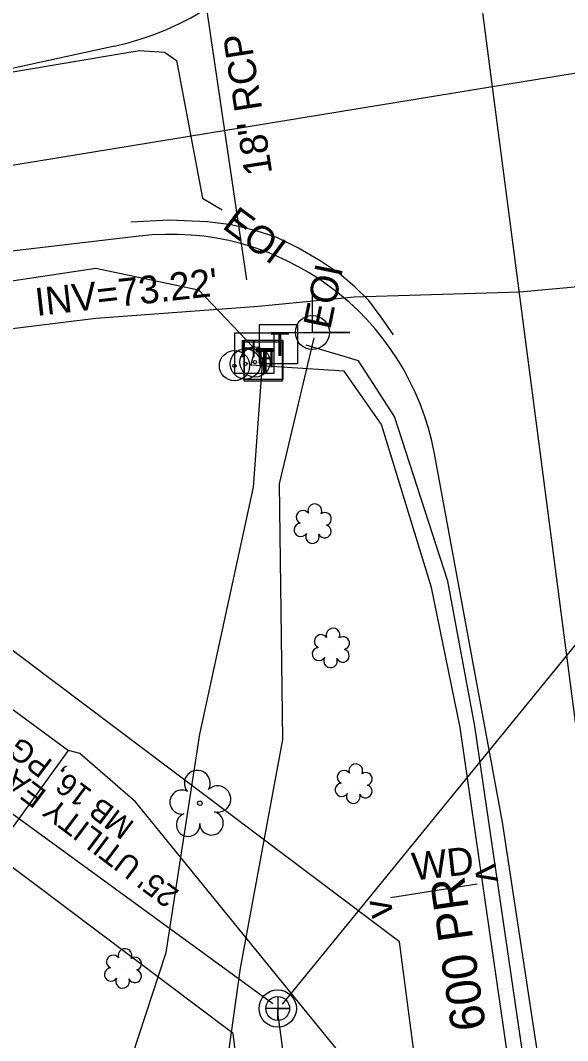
# Model space of a CAD drawing. Extents: x 2364404 to 2371833, y 798876 to 809754.
# Drawn here: x 2368313.6 to 2368392.4, y 807813.1 to 807960.2 of the extents above; entities that cross this region are included whole.
import ezdxf

# ---------------------------------------------------------------- set-up
doc = ezdxf.new("R2010")
doc.units = 0
for name, color, linetype in [('Exist Other Culture Located Object CELL', 7, 'Continuous'), ('Exist Right of Way Easement Line', 7, 'Continuous'), ('Exist Right of Way Easement Line Text', 7, 'Continuous'), ('Exist Right of Way Line', 7, 'Continuous'), ('Exist Roads EOP', 7, 'Continuous'), ('Exist Roads EOT', 7, 'Continuous'), ('Exist Structure Minor Footbridge', 7, 'Continuous'), ('Exist Structure Minor Footbridge Terminator', 7, 'Continuous'), ('Exist Structure Minor Footbridge Text', 7, 'Continuous'), ('Exist Structure Minor Pipes RCP 18 Inch', 7, 'Continuous'), ('Exist Structure Minor Pipes RCP 18 Inch Invert', 7, 'Continuous'), ('Exist Structure Minor Pipes RCP 18 Inch Text', 7, 'Continuous'), ('Exist Utilities Gas UG Line SUE LOS B', 7, 'Continuous'), ('Exist Utilities Other Located Object CELL', 7, 'Continuous'), ('Exist Utilities Other Unknown UG SUE LOS B', 7, 'Continuous'), ('Exist Utilities Other Unknown UG SUE LOS B Text', 7, 'Continuous'), ('Exist Utilities Power Joint Use Telephone CELL', 7, 'Continuous'), ('Exist Utilities Sanitary Sewer Manhole CELL', 7, 'Continuous'), ('Exist Utilities Sanitary Sewer UG Line', 7, 'Continuous'), ('Exist Utilities Telephone Hand Hole CELL', 7, 'Continuous'), ('Exist Utilities Telephone Pedestal CELL', 7, 'Continuous'), ('Exist Utilities Telephone UG Cable SUE LOS C', 7, 'Continuous'), ('Exist Utilities Telephone UG Cable SUE LOS C Text', 7, 'Continuous'), ('Exist Utilities TV UG Cable SUE LOS B', 7, 'Continuous'), ('Exist Utilities Water UG Line SUE LOS B', 7, 'Continuous'), ('Exist Vegetation Shrub CELL', 7, 'Continuous'), ('Exist Vegetation Tree CELL', 7, 'Continuous'), ('Prop Horizontal Alignment', 7, 'Continuous')]:
    doc.layers.add(name, color=color, linetype=linetype)

msp = doc.modelspace()

# ---------------------------------------------------------------- linework, layer by layer
at = {"layer": 'Exist Other Culture Located Object CELL'}
for centre, radius in [((2368347.36, 807910.96), 2.18), ((2368344.41, 807910.43), 2.18), ((2368344.41, 807910.43), 0.24), ((2368347.36, 807910.96), 0.24)]:
    msp.add_circle(centre, radius, dxfattribs=at)
at = {"layer": 'Exist Right of Way Easement Line'}
for p, q in [((2368344.2, 807814.14), (2368262.99, 807875.33)), ((2368511.71, 806538.64), (2368344.2, 807814.14))]:
    msp.add_line(p, q, dxfattribs=at)
at = {"layer": 'Exist Right of Way Line'}
for p, q in [((2368368.2, 807827.36), (2368269.46, 807901.75)), ((2368533.02, 806560.45), (2368368.2, 807827.36))]:
    msp.add_line(p, q, dxfattribs=at)
at = {"layer": 'Exist Roads EOP'}
for points in [[(2368327.15, 807956.52), (2368274.91, 807945.11), (2368232.58, 807936.97), (2368180.11, 807928.25), (2368127.18, 807919.09), (2368078.92, 807911.06), (2368034.07, 807903.44), (2367984.59, 807895.5), (2367945.39, 807888.89), (2367894.54, 807880.53), (2367863.53, 807875.21)], [(2368330.68, 807929.12), (2368282.89, 807923.49), (2368257.36, 807919.77), (2368235.72, 807916.02), (2368181.87, 807907), (2368154.26, 807902.43), (2368131.05, 807898.62), (2368082.95, 807890.29), (2368062.8, 807887.28), (2368038.08, 807883.12), (2367986.91, 807874.75), (2367949.87, 807868.19), (2367928.8, 807864.78), (2367897.29, 807860.14), (2367866.78, 807854.91)], [(2368458.85, 807273.24), (2368452.4, 807323.88), (2368446.15, 807368.12), (2368444.02, 807369.35), (2368441.6, 807369.34), (2368439.16, 807392.12), (2368442.82, 807396.21), (2368435.2, 807454.89), (2368429.11, 807503.15), (2368423.49, 807547.61), (2368418.51, 807586.84), (2368409.79, 807654.27), (2368402.88, 807704.72), (2368396.58, 807752.35), (2368389.7, 807800.7), (2368383.01, 807844.61), (2368373.21, 807897.74)]]:
    msp.add_lwpolyline(points, dxfattribs=at)
for centre, radius, start, end in [((2368318.26, 807997.19), 41.63, 282.3292, 6.5581), ((2368335.2, 807890.73), 38.65, 10.443, 96.7131)]:
    msp.add_arc(centre, radius, start, end, dxfattribs=at)
at = {"layer": 'Exist Roads EOT'}
msp.add_lwpolyline([(2368367.31, 807914.9), (2368365.55, 807917.42), (2368363.75, 807919.85), (2368361.77, 807921.82), (2368359.5, 807923.71), (2368356.75, 807925.55), (2368353.62, 807927.37), (2368350.43, 807928.97), (2368347.53, 807929.88), (2368344, 807930.77), (2368340.52, 807931.16), (2368335.02, 807931.4), (2368329.49, 807931.14)], dxfattribs=at)
at = {"layer": 'Exist Structure Minor Footbridge'}
msp.add_line((2368379.39, 807835.67), (2368366.9, 807833.7), dxfattribs=at)
at = {"layer": 'Exist Structure Minor Pipes RCP 18 Inch'}
msp.add_line((2368339.25, 807969.69), (2368346.16, 807922.83), dxfattribs=at)
at = {"layer": 'Exist Utilities Gas UG Line SUE LOS B'}
msp.add_lwpolyline([(2367870.54, 807838.09), (2367919.9, 807848.3), (2367968.48, 807855.53), (2368019.02, 807864.91), (2368064.26, 807872.88), (2368067.9, 807873.62), (2368094.51, 807877.58), (2368117.72, 807881.71), (2368161.92, 807888.8), (2368216.03, 807898.12), (2368260.65, 807907.32), (2368261.62, 807907.37), (2368282.45, 807912.12), (2368324.46, 807917.31), (2368347.86, 807919.04), (2368361.63, 807920.36), (2368385.5, 807921.08), (2368411.16, 807923.46), (2368412.54, 807923.08), (2368413.42, 807922.79)], dxfattribs=at)
at = {"layer": 'Exist Utilities Other Located Object CELL'}
for radius in [2.18, 0.24]:
    msp.add_circle((2368345.99, 807910.69), radius, dxfattribs=at)
at = {"layer": 'Exist Utilities Other Unknown UG SUE LOS B'}
msp.add_lwpolyline([(2367865.57, 807879.8), (2367916.68, 807886.76), (2367964.49, 807894.84), (2368013.92, 807902.8), (2368064.67, 807911.52), (2368112.58, 807919.65), (2368160.35, 807927.6), (2368209.07, 807936.09), (2368258.24, 807944.17), (2368305.66, 807951.87), (2368307.29, 807951.95), (2368330.7, 807955.87), (2368334.34, 807955.66), (2368336.05, 807954.46), (2368339.82, 807934.59), (2368342.66, 807932.92)], dxfattribs=at)
at = {"layer": 'Exist Utilities Power Joint Use Telephone CELL'}
msp.add_line((2368355.63, 807915.24), (2368355.63, 807915.24), dxfattribs=at)
msp.add_lwpolyline([(2368349.69, 807915.24), (2368361.03, 807915.2), (2368355.63, 807915.22), (2368355.63, 807920.86)], dxfattribs=at)
msp.add_circle((2368355.63, 807915.24), 2.45, dxfattribs=at)
at = {"layer": 'Exist Utilities Sanitary Sewer Manhole CELL'}
msp.add_lwpolyline([(2368350.64, 807819.46), (2368350.64, 807816.04), (2368350.64, 807817.75), (2368352.35, 807817.75), (2368348.93, 807817.75)], dxfattribs=at)
for radius in [2.69, 1.71]:
    msp.add_circle((2368350.64, 807817.75), radius, dxfattribs=at)
at = {"layer": 'Exist Utilities Sanitary Sewer UG Line'}
for p, q in [((2368351.33, 807818.39), (2368447.04, 807935.85)), ((2368349.94, 807818.43), (2368262.9, 807881.9)), ((2368403.25, 807424.76), (2368350.71, 807816.86))]:
    msp.add_line(p, q, dxfattribs=at)
at = {"layer": 'Exist Utilities Telephone Hand Hole CELL'}
for p, q in [((2368344.4, 807915.11), (2368344.4, 807909.38)), ((2368350.12, 807915.11), (2368344.4, 807915.11)), ((2368350.12, 807909.38), (2368350.12, 807915.11)), ((2368347.26, 807912.25), (2368347.26, 807912.25)), ((2368344.4, 807909.38), (2368350.12, 807909.38))]:
    msp.add_line(p, q, dxfattribs=at)
at = {"layer": 'Exist Utilities Telephone Pedestal CELL'}
for p, q in [((2368350.69, 807913.56), (2368350.69, 807913.56)), ((2368348.47, 807911.08), (2368348.47, 807911.08)), ((2368348.56, 807911.3), (2368348.56, 807911.3))]:
    msp.add_line(p, q, dxfattribs=at)
for points in [[(2368347.97, 807910.74), (2368353.56, 807910.74), (2368353.56, 807916.33), (2368347.97, 807916.33), (2368347.97, 807910.74)], [(2368345.75, 807908.25), (2368351.34, 807908.25), (2368351.34, 807913.84), (2368345.75, 807913.84), (2368345.75, 807908.25)], [(2368345.83, 807908.47), (2368351.43, 807908.47), (2368351.43, 807914.07), (2368345.83, 807914.07), (2368345.83, 807908.47)]]:
    msp.add_lwpolyline(points, dxfattribs=at)
at = {"layer": 'Exist Utilities Telephone UG Cable SUE LOS C'}
for points in [[(2368104.4, 807876.72), (2368103.94, 807878.32), (2368103.75, 807883), (2368105.99, 807887.59), (2368109.41, 807889.3), (2368116.46, 807890.7), (2368160.35, 807897.88), (2368214.89, 807907.23), (2368259.58, 807914.4), (2368278.5, 807917.6), (2368324.44, 807924.48), (2368339.22, 807921.35), (2368348.06, 807912.11)], [(2368389.8, 807477.23), (2368411.52, 807479.13), (2368426.75, 807483.79), (2368423.25, 807515.6), (2368416.95, 807563.1), (2368411.16, 807611.97), (2368408.13, 807633.66), (2368404.45, 807661.14), (2368400.96, 807692.3), (2368397.77, 807710.8), (2368392.17, 807754.58), (2368386.02, 807810.85), (2368379.04, 807858.46), (2368375.16, 807879.37), (2368367.44, 807903.09), (2368362.27, 807911.13), (2368354.75, 807913.38)], [(2368318.86, 807794.83), (2368327.7, 807804.86), (2368334.56, 807825.83), (2368339.43, 807857.32), (2368347.17, 807892.9), (2368348.48, 807911.35), (2368348.06, 807912.11)], [(2368377.99, 807750.39), (2368378.54, 807751.1), (2368388.6, 807755.78), (2368389.93, 807760.2), (2368383.78, 807810.78), (2368376.94, 807858.27), (2368372.8, 807878.46), (2368365.61, 807901.95), (2368360.23, 807909.67), (2368346.77, 807910.53), (2368347.26, 807912.25)]]:
    msp.add_lwpolyline(points, dxfattribs=at)
at = {"layer": 'Exist Utilities TV UG Cable SUE LOS B'}
msp.add_lwpolyline([(2368355.84, 807914.45), (2368350.87, 807893.41), (2368351.33, 807856.53), (2368345.22, 807823.55), (2368340.94, 807792.99), (2368324.42, 807779.98), (2368309.01, 807768.03), (2368294.55, 807764.63), (2368287.14, 807772.6), (2368278.55, 807795.28), (2368279.58, 807798.84)], dxfattribs=at)
at = {"layer": 'Exist Utilities Water UG Line SUE LOS B'}
for points in [[(2368262.53, 807894.28), (2368285.49, 807880.7), (2368320.49, 807854.97)], [(2368309.28, 807839.68), (2368309.67, 807840.02), (2368320.49, 807854.97)], [(2368370.41, 807753.28), (2368370.1, 807758.01), (2368363.49, 807806.54), (2368330.15, 807847.55), (2368322.15, 807854.5), (2368320.49, 807854.97)]]:
    msp.add_lwpolyline(points, dxfattribs=at)
at = {"layer": 'Exist Vegetation Shrub CELL'}
for p, q in [((2368355.76, 807887.47), (2368355.76, 807887.47)), ((2368358.37, 807869.56), (2368358.37, 807869.56)), ((2368361.66, 807849.99), (2368361.66, 807849.99)), ((2368328.42, 807823.34), (2368328.42, 807823.34))]:
    msp.add_line(p, q, dxfattribs=at)
for centre, radius, start, end in [((2368354.28, 807888.6), 0.968, 35.8908, 245.4216), ((2368355.99, 807889.51), 0.99, 334.8391, 200.4717), ((2368357.44, 807888.34), 0.929, 284.4567, 126.0861), ((2368353.96, 807886.76), 0.955, 95.1099, 327.9534), ((2368357.4, 807886.54), 0.937, 204.9913, 73.4601), ((2368355.64, 807885.78), 0.984, 151.2797, 21.387), ((2368358.6, 807871.6), 0.99, 334.8391, 200.4717), ((2368356.89, 807870.69), 0.968, 35.8908, 245.4216), ((2368360.04, 807870.43), 0.929, 284.4567, 126.0861), ((2368356.57, 807868.86), 0.955, 95.1099, 327.9534), ((2368360.01, 807868.63), 0.937, 204.9913, 73.4601), ((2368358.24, 807867.88), 0.984, 151.2797, 21.387), ((2368361.89, 807852.03), 0.99, 334.8391, 200.4717), ((2368360.18, 807851.11), 0.968, 35.8908, 245.4216), ((2368363.33, 807850.85), 0.929, 284.4567, 126.0861), ((2368359.86, 807849.28), 0.955, 95.1099, 327.9534), ((2368363.29, 807849.06), 0.937, 204.9913, 73.4601), ((2368361.53, 807848.3), 0.984, 151.2797, 21.387), ((2368328.65, 807825.38), 0.99, 334.8391, 200.4717), ((2368326.94, 807824.47), 0.968, 35.8908, 245.4216), ((2368330.1, 807824.21), 0.929, 284.4567, 126.0861), ((2368326.62, 807822.64), 0.955, 95.1099, 327.9534), ((2368328.3, 807821.66), 0.984, 151.2797, 21.387), ((2368330.06, 807822.41), 0.937, 204.9913, 73.4601)]:
    msp.add_arc(centre, radius, start, end, dxfattribs=at)
at = {"layer": 'Exist Vegetation Tree CELL'}
msp.add_line((2368339.43, 807847.36), (2368339.43, 807847.36), dxfattribs=at)
msp.add_circle((2368339.43, 807847.36), 0.326, dxfattribs=at)
for centre, radius, start, end in [((2368339.05, 807850.23), 1.86, 330.1651, 219.7134), ((2368341.98, 807847.95), 1.9, 257.1011, 134.1999), ((2368336.83, 807847.52), 1.73, 62.6636, 279.3457), ((2368337.73, 807844.24), 1.69, 111.5671, 6.231), ((2368341.1, 807844.46), 1.7, 181.2822, 74.56)]:
    msp.add_arc(centre, radius, start, end, dxfattribs=at)
at = {"layer": 'Prop Horizontal Alignment'}
for p, q in [((2368427.27, 807599.89), (2368315.24, 808460.34)), ((2368381.6, 807950.7), (2368895.64, 808034.91)), ((2368281.91, 807934.37), (2368381.6, 807950.7))]:
    msp.add_line(p, q, dxfattribs=at)

# ---------------------------------------------------------------- texts
at = {"layer": 'Exist Right of Way Easement Line Text'}
for s, p in [("25' UTILITY EASEMENT", (2368336.6, 807834.62)), ('MB 16, PG 35', (2368330.16, 807844.49))]:
    msp.add_text(s, height=3.2, rotation=143.0041, dxfattribs=at).set_placement(p)
at = {"layer": 'Exist Structure Minor Footbridge Terminator'}
for rotation, p in [(278.9517, (2368378.97, 807838.28)), (98.9517, (2368367.31, 807831.09))]:
    msp.add_text('v', height=4, rotation=rotation, dxfattribs=at).set_placement(p)
at = {"layer": 'Exist Structure Minor Footbridge Text'}
msp.add_text('WD', height=4, rotation=6.3435, dxfattribs=at).set_placement((2368370.21, 807836.2))
at = {"layer": 'Exist Structure Minor Pipes RCP 18 Inch Invert'}
msp.add_text("INV=73.22'", height=4, rotation=6.4313, dxfattribs=at).set_placement((2368315.91, 807917.6))
at = {"layer": 'Exist Structure Minor Pipes RCP 18 Inch Text'}
msp.add_text('18" RCP', height=4, rotation=98.9085, dxfattribs=at).set_placement((2368349.87, 807938.2))
at = {"layer": 'Exist Utilities Other Unknown UG SUE LOS B Text'}
msp.add_text('EOI', height=4, rotation=323.395, dxfattribs=at).set_placement((2368342.49, 807930.37))
at = {"layer": 'Exist Utilities Telephone Hand Hole CELL'}
for p in [(2368345.18, 807911.65), (2368347.75, 807910.19)]:
    msp.add_text('H', height=2.5, dxfattribs=at).set_placement(p)
at = {"layer": 'Exist Utilities Telephone Pedestal CELL'}
for p in [(2368349.56, 807911.85), (2368347.34, 807909.36), (2368347.43, 807909.59)]:
    msp.add_text('T', height=3.42, dxfattribs=at).set_placement(p)
at = {"layer": 'Exist Utilities Telephone UG Cable SUE LOS C Text'}
for s, height, rotation, p in [('EOI', 4, 78.2193, (2368358.2, 807915.54)), ('600 PR', 5, 98.1889, (2368380.66, 807814.91))]:
    msp.add_text(s, height=height, rotation=rotation, dxfattribs=at).set_placement(p)

doc.saveas('drawing.dxf')
